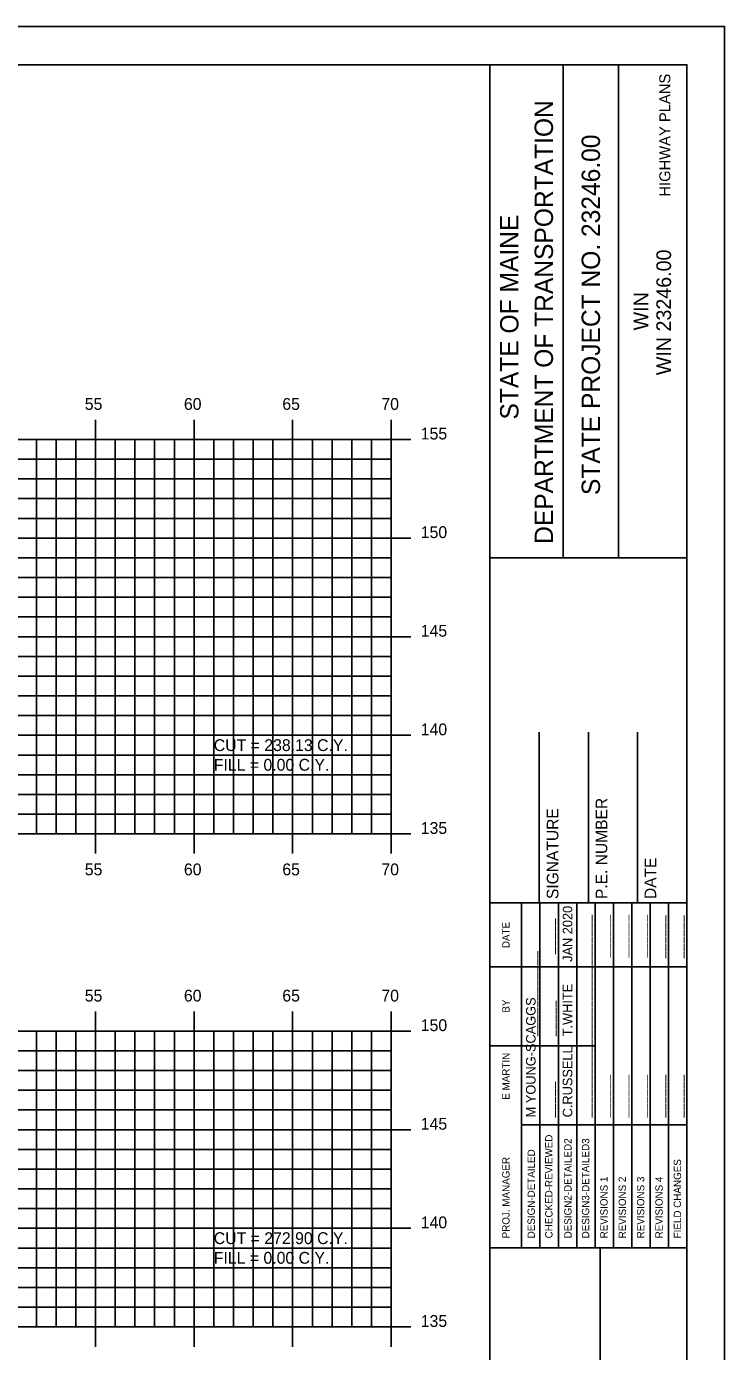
# Model space of a CAD drawing. Extents: x 1144529 to 1144699, y 608981 to 609091.
# Drawn here: x 1144663.4 to 1144698.8, y 609024.1 to 609091.3 of the extents above; entities that cross this region are included whole.
import ezdxf

# ---------------------------------------------------------------- set-up
doc = ezdxf.new("R2010")
doc.units = 0
for name, color, linetype in [('BORDER', 7, 'Continuous'), ('D_Text_Standard', 7, 'Continuous'), ('H_V ANNOTATION', 7, 'Continuous'), ('HIGHWAY_TITLE', 7, 'Continuous'), ('MAJOR', 7, 'Continuous'), ('MINOR', 7, 'Continuous'), ('PLOT BOUNDARY', 7, 'Continuous')]:
    doc.layers.add(name, color=color, linetype=linetype)

msp = doc.modelspace()

# ---------------------------------------------------------------- linework, layer by layer
at = {"layer": 'BORDER'}
for p, q in [((1144686.863, 608984.335), (1144686.863, 609089.335)), ((1144690.591, 609064.332), (1144690.591, 609089.332)), ((1144693.386, 609064.332), (1144693.386, 609089.332)), ((1144686.863, 609064.329), (1144696.863, 609064.329)), ((1144689.363, 609046.838), (1144689.363, 609055.485)), ((1144691.863, 609046.838), (1144691.863, 609055.485)), ((1144694.363, 609046.838), (1144694.363, 609055.485)), ((1144686.863, 609046.838), (1144696.863, 609046.838)), ((1144686.863, 609029.338), (1144696.863, 609029.338)), ((1144692.454, 608994.338), (1144692.454, 609029.338))]:
    msp.add_line(p, q, dxfattribs=at)
msp.add_lwpolyline([(1144536.863, 608984.335), (1144696.863, 608984.335), (1144696.863, 609089.335), (1144536.863, 609089.335)], close=True, dxfattribs=at)
for points in [[(1144688.477, 609043.588), (1144688.477, 609046.838)], [(1144689.41, 609029.341), (1144689.41, 609046.838)], [(1144690.342, 609046.838), (1144690.342, 609029.341)], [(1144691.273, 609029.341), (1144691.273, 609046.838)], [(1144692.205, 609029.341), (1144692.205, 609046.838)], [(1144693.137, 609029.341), (1144693.137, 609046.838)], [(1144694.068, 609029.341), (1144694.068, 609046.838)], [(1144695, 609029.341), (1144695, 609046.838)], [(1144695.932, 609029.341), (1144695.932, 609046.838)], [(1144688.478, 609029.341), (1144688.478, 609046.132)], [(1144686.863, 609043.588), (1144696.863, 609043.588)], [(1144686.863, 609039.588), (1144688.478, 609039.588)], [(1144688.477, 609039.588), (1144692.204, 609039.588)], [(1144688.477, 609035.588), (1144696.863, 609035.588)]]:
    msp.add_lwpolyline(points, dxfattribs=at)
at = {"layer": 'MAJOR'}
for p, q in [((1144666.862, 609071.337), (1144666.862, 609070.335)), ((1144671.862, 609071.337), (1144671.862, 609070.335)), ((1144676.862, 609071.337), (1144676.862, 609070.335)), ((1144681.862, 609071.337), (1144681.862, 609070.335)), ((1144541.862, 609070.335), (1144681.862, 609070.335)), ((1144541.862, 609070.335), (1144681.862, 609070.335)), ((1144666.862, 609050.335), (1144666.862, 609070.335)), ((1144671.862, 609050.335), (1144671.862, 609070.335)), ((1144676.862, 609050.335), (1144676.862, 609070.335)), ((1144682.864, 609070.335), (1144680.86, 609070.335)), ((1144681.862, 609050.335), (1144681.862, 609070.335)), ((1144681.862, 609050.335), (1144681.862, 609070.335)), ((1144541.862, 609065.335), (1144681.862, 609065.335)), ((1144682.864, 609065.335), (1144680.86, 609065.335)), ((1144541.862, 609060.335), (1144681.862, 609060.335)), ((1144682.864, 609060.335), (1144680.86, 609060.335)), ((1144541.862, 609055.335), (1144681.862, 609055.335)), ((1144682.864, 609055.335), (1144680.86, 609055.335)), ((1144541.862, 609050.335), (1144681.862, 609050.335)), ((1144541.862, 609050.335), (1144681.862, 609050.335)), ((1144666.862, 609049.333), (1144666.862, 609050.335)), ((1144671.862, 609049.333), (1144671.862, 609050.335)), ((1144676.862, 609049.333), (1144676.862, 609050.335)), ((1144682.864, 609050.335), (1144680.86, 609050.335)), ((1144681.862, 609049.333), (1144681.862, 609050.335)), ((1144666.862, 609041.337), (1144666.862, 609040.335)), ((1144671.862, 609041.337), (1144671.862, 609040.335)), ((1144676.862, 609041.337), (1144676.862, 609040.335)), ((1144681.862, 609041.337), (1144681.862, 609040.335)), ((1144541.862, 609040.335), (1144681.862, 609040.335)), ((1144541.862, 609040.335), (1144681.862, 609040.335)), ((1144666.862, 609025.335), (1144666.862, 609040.335)), ((1144671.862, 609025.335), (1144671.862, 609040.335)), ((1144676.862, 609025.335), (1144676.862, 609040.335)), ((1144682.864, 609040.335), (1144680.86, 609040.335)), ((1144681.862, 609025.335), (1144681.862, 609040.335)), ((1144681.862, 609025.335), (1144681.862, 609040.335)), ((1144541.862, 609035.335), (1144681.862, 609035.335)), ((1144682.864, 609035.335), (1144680.86, 609035.335)), ((1144541.862, 609030.335), (1144681.862, 609030.335)), ((1144682.864, 609030.335), (1144680.86, 609030.335)), ((1144541.862, 609025.335), (1144681.862, 609025.335)), ((1144541.862, 609025.335), (1144681.862, 609025.335)), ((1144666.862, 609024.333), (1144666.862, 609025.335)), ((1144671.862, 609024.333), (1144671.862, 609025.335)), ((1144676.862, 609024.333), (1144676.862, 609025.335)), ((1144682.864, 609025.335), (1144680.86, 609025.335)), ((1144681.862, 609024.333), (1144681.862, 609025.335))]:
    msp.add_line(p, q, dxfattribs=at)
at = {"layer": 'MINOR'}
for p, q in [((1144663.862, 609050.335), (1144663.862, 609070.335)), ((1144664.862, 609050.335), (1144664.862, 609070.335)), ((1144665.862, 609050.335), (1144665.862, 609070.335)), ((1144667.862, 609050.335), (1144667.862, 609070.335)), ((1144668.862, 609050.335), (1144668.862, 609070.335)), ((1144669.862, 609050.335), (1144669.862, 609070.335)), ((1144670.862, 609050.335), (1144670.862, 609070.335)), ((1144672.862, 609050.335), (1144672.862, 609070.335)), ((1144673.862, 609050.335), (1144673.862, 609070.335)), ((1144674.862, 609050.335), (1144674.862, 609070.335)), ((1144675.862, 609050.335), (1144675.862, 609070.335)), ((1144677.862, 609050.335), (1144677.862, 609070.335)), ((1144678.862, 609050.335), (1144678.862, 609070.335)), ((1144679.862, 609050.335), (1144679.862, 609070.335)), ((1144680.862, 609050.335), (1144680.862, 609070.335)), ((1144541.862, 609069.335), (1144681.862, 609069.335)), ((1144681.862, 609069.335), (1144680.86, 609069.335)), ((1144541.862, 609068.335), (1144681.862, 609068.335)), ((1144681.862, 609068.335), (1144680.86, 609068.335)), ((1144541.862, 609067.335), (1144681.862, 609067.335)), ((1144681.862, 609067.335), (1144680.86, 609067.335)), ((1144541.862, 609066.335), (1144681.862, 609066.335)), ((1144681.862, 609066.335), (1144680.86, 609066.335)), ((1144541.862, 609064.335), (1144681.862, 609064.335)), ((1144681.862, 609064.335), (1144680.86, 609064.335)), ((1144541.862, 609063.335), (1144681.862, 609063.335)), ((1144681.862, 609063.335), (1144680.86, 609063.335)), ((1144541.862, 609062.335), (1144681.862, 609062.335)), ((1144681.862, 609062.335), (1144680.86, 609062.335)), ((1144541.862, 609061.335), (1144681.862, 609061.335)), ((1144681.862, 609061.335), (1144680.86, 609061.335)), ((1144541.862, 609059.335), (1144681.862, 609059.335)), ((1144681.862, 609059.335), (1144680.86, 609059.335)), ((1144541.862, 609058.335), (1144681.862, 609058.335)), ((1144681.862, 609058.335), (1144680.86, 609058.335)), ((1144541.862, 609057.335), (1144681.862, 609057.335)), ((1144681.862, 609057.335), (1144680.86, 609057.335)), ((1144541.862, 609056.335), (1144681.862, 609056.335)), ((1144681.862, 609056.335), (1144680.86, 609056.335)), ((1144541.862, 609054.335), (1144681.862, 609054.335)), ((1144681.862, 609054.335), (1144680.86, 609054.335)), ((1144541.862, 609053.335), (1144681.862, 609053.335)), ((1144681.862, 609053.335), (1144680.86, 609053.335)), ((1144541.862, 609052.335), (1144681.862, 609052.335)), ((1144681.862, 609052.335), (1144680.86, 609052.335)), ((1144541.862, 609051.335), (1144681.862, 609051.335)), ((1144681.862, 609051.335), (1144680.86, 609051.335)), ((1144663.862, 609025.335), (1144663.862, 609040.335)), ((1144664.862, 609025.335), (1144664.862, 609040.335)), ((1144665.862, 609025.335), (1144665.862, 609040.335)), ((1144667.862, 609025.335), (1144667.862, 609040.335)), ((1144668.862, 609025.335), (1144668.862, 609040.335)), ((1144669.862, 609025.335), (1144669.862, 609040.335)), ((1144670.862, 609025.335), (1144670.862, 609040.335)), ((1144672.862, 609025.335), (1144672.862, 609040.335)), ((1144673.862, 609025.335), (1144673.862, 609040.335)), ((1144674.862, 609025.335), (1144674.862, 609040.335)), ((1144675.862, 609025.335), (1144675.862, 609040.335)), ((1144677.862, 609025.335), (1144677.862, 609040.335)), ((1144678.862, 609025.335), (1144678.862, 609040.335)), ((1144679.862, 609025.335), (1144679.862, 609040.335)), ((1144680.862, 609025.335), (1144680.862, 609040.335)), ((1144541.862, 609039.335), (1144681.862, 609039.335)), ((1144681.862, 609039.335), (1144680.86, 609039.335)), ((1144541.862, 609038.335), (1144681.862, 609038.335)), ((1144681.862, 609038.335), (1144680.86, 609038.335)), ((1144541.862, 609037.335), (1144681.862, 609037.335)), ((1144681.862, 609037.335), (1144680.86, 609037.335)), ((1144541.862, 609036.335), (1144681.862, 609036.335)), ((1144681.862, 609036.335), (1144680.86, 609036.335)), ((1144541.862, 609034.335), (1144681.862, 609034.335)), ((1144681.862, 609034.335), (1144680.86, 609034.335)), ((1144541.862, 609033.335), (1144681.862, 609033.335)), ((1144681.862, 609033.335), (1144680.86, 609033.335)), ((1144541.862, 609032.335), (1144681.862, 609032.335)), ((1144681.862, 609032.335), (1144680.86, 609032.335)), ((1144541.862, 609031.335), (1144681.862, 609031.335)), ((1144681.862, 609031.335), (1144680.86, 609031.335)), ((1144541.862, 609029.335), (1144681.862, 609029.335)), ((1144681.862, 609029.335), (1144680.86, 609029.335)), ((1144541.862, 609028.335), (1144681.862, 609028.335)), ((1144681.862, 609028.335), (1144680.86, 609028.335)), ((1144541.862, 609027.335), (1144681.862, 609027.335)), ((1144681.862, 609027.335), (1144680.86, 609027.335)), ((1144541.862, 609026.335), (1144681.862, 609026.335)), ((1144681.862, 609026.335), (1144680.86, 609026.335))]:
    msp.add_line(p, q, dxfattribs=at)
at = {"layer": 'PLOT BOUNDARY'}
msp.add_lwpolyline([(1144528.769, 608981.276), (1144698.769, 608981.276), (1144698.769, 609091.276), (1144528.769, 609091.276)], close=True, dxfattribs=at)

# ---------------------------------------------------------------- texts
at = {"layer": 'BORDER'}
for s, height, p in [('DEPARTMENT OF TRANSPORTATION', 0.93176, (1144690.069, 609065.041)), ('STATE PROJECT NO. 23246.00', 0.93176, (1144692.454, 609067.517)), ('STATE OF MAINE', 0.93176, (1144688.318, 609071.347)), ('WIN 23246.00', 0.74527, (1144696.058, 609073.596)), ('WIN', 0.7453, (1144694.899, 609075.865)), ('P.E. NUMBER', 0.59055, (1144692.823, 609047.03)), ('SIGNATURE', 0.5906, (1144690.343, 609047.03)), ('DATE', 0.5906, (1144695.304, 609047.03)), ('JAN 2020', 0.4845, (1144691.049, 609043.843)), ('DATE', 0.3714, (1144687.867, 609044.544)), ('_____', 0.4845, (1144690.08, 609044.243)), ('______', 0.4845, (1144691.943, 609044.063)), ('______', 0.4845, (1144692.875, 609044.065)), ('______', 0.4845, (1144693.807, 609044.067)), ('______', 0.4845, (1144694.738, 609044.067)), ('______', 0.4845, (1144695.67, 609044.036)), ('______', 0.4845, (1144696.602, 609044.036)), ('____________', 0.48455, (1144689.185, 609040.073)), ('____________', 0.48455, (1144691.943, 609040.073)), ('T.WHITE', 0.4845, (1144691.049, 609040.073)), ('BY', 0.3714, (1144687.867, 609041.273)), ('M YOUNG-SCAGGS', 0.48455, (1144689.185, 609035.961)), ('_____', 0.4845, (1144690.117, 609040.073)), ('____________', 0.48455, (1144691.943, 609035.961)), ('E MARTIN', 0.3727, (1144687.867, 609036.855)), ('C.RUSSELL', 0.4845, (1144691.049, 609035.961)), ('_____', 0.4845, (1144690.08, 609035.961)), ('______', 0.4845, (1144692.875, 609035.961)), ('______', 0.4845, (1144693.807, 609035.961)), ('______', 0.4845, (1144694.738, 609035.961)), ('______', 0.4845, (1144695.67, 609035.961)), ('______', 0.4845, (1144696.602, 609035.961)), ('CHECKED-REVIEWED', 0.37275, (1144690.044, 609029.826)), ('DESIGN2-DETAILED2', 0.37275, (1144691.012, 609029.826)), ('DESIGN3-DETAILED3', 0.37275, (1144691.907, 609029.826)), ('DESIGN-DETAILED', 0.37275, (1144689.149, 609029.826)), ('PROJ. MANAGER', 0.37275, (1144687.867, 609029.826)), ('FIELD CHANGES', 0.37275, (1144696.565, 609029.826)), ('REVISIONS 1', 0.37275, (1144692.839, 609029.826)), ('REVISIONS 2', 0.37275, (1144693.77, 609029.826)), ('REVISIONS 3', 0.37275, (1144694.702, 609029.826)), ('REVISIONS 4', 0.37275, (1144695.634, 609029.826))]:
    msp.add_text(s, height=height, rotation=90, dxfattribs=at).set_placement(p)
at = {"layer": 'D_Text_Standard'}
for s, p in [('CUT = 238.13 C.Y.', (1144672.862, 609054.535)), ('FILL = 0.00 C.Y.', (1144672.862, 609053.539)), ('CUT = 272.90 C.Y.', (1144672.862, 609029.535)), ('FILL = 0.00 C.Y.', (1144672.862, 609028.539))]:
    msp.add_text(s, height=0.6, dxfattribs=at).set_placement(p)
at = {"layer": 'H_V ANNOTATION'}
for s, p in [('55', (1144666.319, 609071.835)), ('60', (1144671.348, 609071.835)), ('65', (1144676.34, 609071.835)), ('70', (1144681.364, 609071.835)), ('155', (1144683.362, 609070.335)), ('150', (1144683.362, 609065.335)), ('145', (1144683.362, 609060.335)), ('140', (1144683.362, 609055.335)), ('135', (1144683.362, 609050.335)), ('55', (1144666.319, 609048.235)), ('60', (1144671.348, 609048.235)), ('65', (1144676.34, 609048.235)), ('70', (1144681.364, 609048.235)), ('55', (1144666.319, 609041.835)), ('60', (1144671.348, 609041.835)), ('65', (1144676.34, 609041.835)), ('70', (1144681.364, 609041.835)), ('150', (1144683.362, 609040.335)), ('145', (1144683.362, 609035.335)), ('140', (1144683.362, 609030.335)), ('135', (1144683.362, 609025.335))]:
    msp.add_text(s, height=0.6, dxfattribs=at).set_placement(p)
at = {"layer": 'HIGHWAY_TITLE'}
msp.add_text('HIGHWAY PLANS', height=0.55901, rotation=90, dxfattribs=at).set_placement((1144696.021, 609082.65))

doc.saveas('drawing.dxf')
